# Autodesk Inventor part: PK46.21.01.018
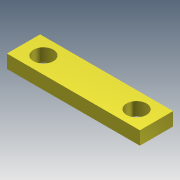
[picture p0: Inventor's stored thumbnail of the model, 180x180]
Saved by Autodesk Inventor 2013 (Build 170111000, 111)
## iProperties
Created: 2005-04
Part Number: PK46.21.01.018
Material: Steel, Mild
Document SubType Name: Modeling
Designer: salex
Manufacturer: Standard
Standards Organization: Custom
Density: 7.86 g/cm^3
Author: salex
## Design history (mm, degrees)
sketch "Эскиз1"
  geometry: L1 (0, 0)-(200, 0); L2 (200, 0)-(200, 50); L3 (200, 50)-(0, 50); L4 (0, 50)-(0, 0); C1 r 15 at (30, 25); C2 r 15 at (170, 25)
  constraints: 8 end point, 2 centre point, 2 parallel, 1 equal radius, 1 horizontal, 1 perpendicular, 1 other
  dimensions: "d0" = 200 distance between parallel lines of L2 L4; "d1" = 50 distance of L3.end L1.start; "d2" = 140 distance of C2.centre C1.centre; "d3" = 0 vertical distance of C2.centre C1.centre; "d4" = 25 distance from line of L1 C1.centre (= 0.5 x d1); "d5" = 30 diameter of C1; "d6" = 30 distance from line of L4 C1.centre
extrude "Выдавливание1" new body sketch "Эскиз1" distance "d7" = 20; taper "d8" = 0 deg
body "Solid1"
